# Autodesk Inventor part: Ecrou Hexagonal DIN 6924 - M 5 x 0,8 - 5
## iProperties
Created: 2002-06
Part Number: Ecrou Hexagonal DIN 6924 - M 5 x 0,8 - 5
Material: Par défaut
Catalog Web Link: www.traceparts.com
Description: Ecrou Hexagonal DIN 6924 - M 5 x 0,8 - 5
Document SubType Name: Modélisation
Designer: Maison
Control State: 0
Master: False
Checked Out: False
Shininess: 20.0
Length Units: 11269
Angle Units: 11279
Time Units: 11290
Mass Units: 11283
Length Display Precision: 3
Angle Display Precision: 2
Density: 0.0
Volumn: 0.0
Area: 0.0
PropertySet Name: Model Information
Author: Maison
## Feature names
1. Base1
